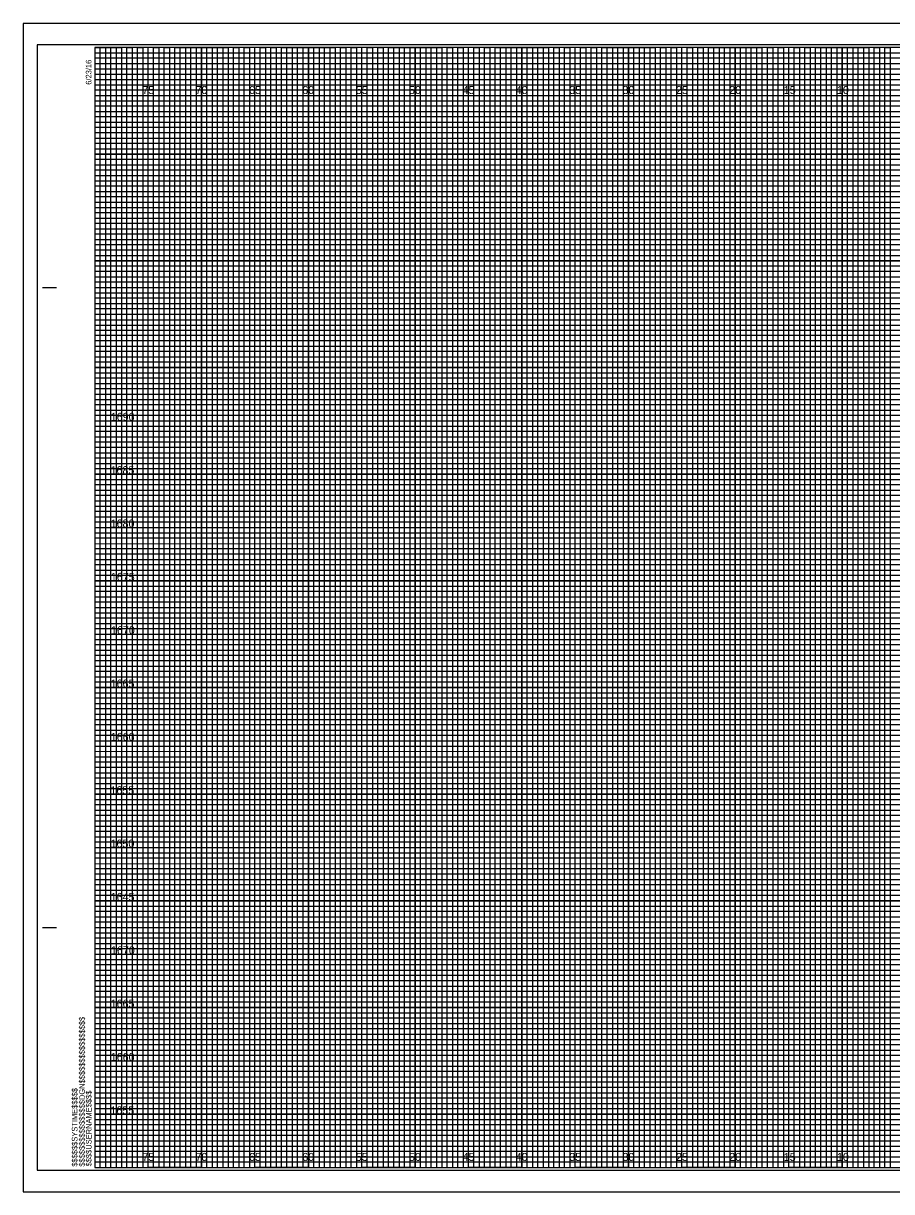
# Model space of a CAD drawing. Extents: x 224 to 392, y 1 to 440.
# Drawn here: x 223.6 to 304.9, y 1 to 110.5 of the extents above; entities that cross this region are included whole.
import ezdxf

# ---------------------------------------------------------------- set-up
doc = ezdxf.new("R2010")
doc.units = 0
for name, color, linetype in [('Prop Grid Mask', 7, 'Continuous'), ('Prop XS Elevation Labels', 7, 'Continuous'), ('Sheet Cross Section CELL', 7, 'Continuous'), ('Sheet Cross Section Grid Major CELL', 7, 'Continuous'), ('Sheet Cross Section Grid Middle CELL', 7, 'Continuous'), ('Sheet Cross Section Grid Minor 1 CELL', 7, 'Continuous'), ('Sheet Cross Section Grid Minor 2 CELL', 7, 'Continuous'), ('Sheet Cutting Line CELL', 7, 'Continuous'), ('Sheet DOT Grid CELL', 7, 'Continuous'), ('Sheet Plot Border Inside CELL', 7, 'Continuous'), ('Sheet Plot Border Outside CELL', 7, 'Continuous')]:
    doc.layers.add(name, color=color, linetype=linetype)

msp = doc.modelspace()

# ---------------------------------------------------------------- linework, layer by layer
at = {"layer": 'Sheet Cross Section CELL'}
for p, q in [((225.36, 85.71), (226.61, 85.71)), ((225.41, 85.71), (226.66, 85.71)), ((225.36, 25.71), (226.61, 25.71)), ((225.41, 25.71), (226.66, 25.71)), ((230.26, 3.21), (230.26, 3.21)), ((230.26, 3.21), (230.26, 3.21)), ((230.26, 3.21), (230.26, 3.21)), ((230.26, 3.21), (230.26, 3.21)), ((230.26, 3.21), (230.26, 3.21)), ((230.26, 3.21), (230.26, 3.21)), ((230.26, 3.21), (230.26, 3.21))]:
    msp.add_line(p, q, dxfattribs=at)
msp.add_lwpolyline([(390.26, 108.21), (230.26, 108.21), (230.26, 3.21), (390.26, 3.21)], close=True, dxfattribs=at)
at = {"layer": 'Sheet Cross Section Grid Major CELL'}
for p, q in [((235.26, 108.21), (230.26, 108.21)), ((235.26, 3.21), (235.26, 108.21)), ((245.26, 108.21), (240.26, 108.21)), ((240.26, 108.21), (240.26, 3.21)), ((245.26, 3.21), (245.26, 108.21)), ((255.26, 108.21), (250.26, 108.21)), ((250.26, 108.21), (250.26, 3.21)), ((255.26, 3.21), (255.26, 108.21)), ((265.26, 108.21), (260.26, 108.21)), ((260.26, 108.21), (260.26, 3.21)), ((265.26, 3.21), (265.26, 108.21)), ((275.26, 108.21), (270.26, 108.21)), ((270.26, 108.21), (270.26, 3.21)), ((275.26, 3.21), (275.26, 108.21)), ((285.26, 108.21), (280.26, 108.21)), ((280.26, 108.21), (280.26, 3.21)), ((285.26, 3.21), (285.26, 108.21)), ((295.26, 108.21), (290.26, 108.21)), ((290.26, 108.21), (290.26, 3.21)), ((295.26, 3.21), (295.26, 108.21)), ((305.26, 108.21), (300.26, 108.21)), ((300.26, 108.21), (300.26, 3.21)), ((240.26, 3.21), (235.26, 3.21)), ((250.26, 3.21), (245.26, 3.21)), ((260.26, 3.21), (255.26, 3.21)), ((270.26, 3.21), (265.26, 3.21)), ((280.26, 3.21), (275.26, 3.21)), ((290.26, 3.21), (285.26, 3.21)), ((300.26, 3.21), (295.26, 3.21))]:
    msp.add_line(p, q, dxfattribs=at)
for points in [[(230.26, 103.21), (390.26, 103.21), (390.26, 98.21), (230.26, 98.21)], [(230.26, 93.21), (390.26, 93.21), (390.26, 88.21), (230.26, 88.21)], [(230.26, 83.21), (390.26, 83.21), (390.26, 78.21), (230.26, 78.21)], [(230.26, 73.21), (390.26, 73.21), (390.26, 68.21), (230.26, 68.21)], [(230.26, 63.21), (390.26, 63.21), (390.26, 58.21), (230.26, 58.21)], [(230.26, 53.21), (390.26, 53.21), (390.26, 48.21), (230.26, 48.21)], [(230.26, 43.21), (390.26, 43.21), (390.26, 38.21), (230.26, 38.21)], [(230.26, 33.21), (390.26, 33.21), (390.26, 28.21), (230.26, 28.21)], [(230.26, 23.21), (390.26, 23.21), (390.26, 18.21), (230.26, 18.21)], [(230.26, 13.21), (390.26, 13.21), (390.26, 8.21), (230.26, 8.21)]]:
    msp.add_lwpolyline(points, dxfattribs=at)
at = {"layer": 'Sheet Cross Section Grid Middle CELL'}
for points in [[(230.26, 108.21), (232.76, 108.21), (232.76, 3.21), (237.76, 3.21), (237.76, 108.21), (242.76, 108.21), (242.76, 3.21), (247.76, 3.21), (247.76, 108.21), (252.76, 108.21), (252.76, 3.21), (257.76, 3.21), (257.76, 108.21), (262.76, 108.21), (262.76, 3.21), (267.76, 3.21), (267.76, 108.21), (272.76, 108.21), (272.76, 3.21), (277.76, 3.21), (277.76, 108.21), (282.76, 108.21), (282.76, 3.21), (287.76, 3.21), (287.76, 108.21), (292.76, 108.21), (292.76, 3.21), (297.76, 3.21), (297.76, 108.21), (302.76, 108.21), (302.76, 3.21), (307.76, 3.21)], [(230.26, 105.71), (367.76, 105.71)], [(230.26, 95.71), (390.26, 95.71), (390.26, 100.71), (230.26, 100.71)], [(230.26, 85.71), (390.26, 85.71), (390.26, 90.71), (230.26, 90.71)], [(230.26, 75.71), (390.26, 75.71), (390.26, 80.71), (230.26, 80.71)], [(230.26, 65.71), (390.26, 65.71), (390.26, 70.71), (230.26, 70.71)], [(230.26, 55.71), (390.26, 55.71), (390.26, 60.71), (230.26, 60.71)], [(230.26, 45.71), (390.26, 45.71), (390.26, 50.71), (230.26, 50.71)], [(230.26, 35.71), (390.26, 35.71), (390.26, 40.71), (230.26, 40.71)], [(230.26, 25.71), (390.26, 25.71), (390.26, 30.71), (230.26, 30.71)], [(230.26, 15.71), (390.26, 15.71), (390.26, 20.71), (230.26, 20.71)], [(230.26, 5.71), (390.26, 5.71), (390.26, 10.71), (230.26, 10.71)]]:
    msp.add_lwpolyline(points, dxfattribs=at)
at = {"layer": 'Sheet Cross Section Grid Minor 1 CELL'}
for p, q in [((230.26, 107.71), (360.26, 107.71)), ((360.26, 107.2), (230.26, 107.2)), ((230.26, 107.2), (230.26, 106.71)), ((230.26, 106.71), (360.26, 106.71)), ((360.26, 106.16), (230.26, 106.16)), ((230.26, 106.16), (230.26, 105.21)), ((230.26, 105.21), (390.26, 105.21))]:
    msp.add_line(p, q, dxfattribs=at)
for points in [[(230.26, 104.71), (365.26, 104.71), (390.26, 104.71), (390.26, 104.21), (230.26, 104.21)], [(230.26, 103.71), (390.26, 103.71), (390.26, 102.71), (230.26, 102.71)], [(230.26, 102.21), (390.26, 102.21), (390.26, 101.71), (230.26, 101.7)], [(230.26, 101.21), (390.26, 101.21), (390.26, 100.21), (230.26, 100.21)], [(230.26, 99.71), (390.26, 99.71), (390.26, 99.21), (230.26, 99.21)], [(230.26, 98.71), (390.26, 98.71), (390.26, 97.71), (230.26, 97.71)], [(230.26, 97.21), (390.26, 97.21), (390.26, 96.71), (230.26, 96.71)], [(230.26, 96.21), (390.26, 96.21), (390.26, 95.21), (230.26, 95.21)], [(230.26, 94.71), (390.26, 94.71), (390.26, 94.21), (230.26, 94.21)], [(230.26, 93.71), (390.26, 93.71), (390.26, 92.71), (230.26, 92.71)], [(230.26, 92.21), (390.26, 92.21), (390.26, 91.71), (230.26, 91.71)], [(230.26, 91.21), (390.26, 91.21), (390.26, 90.19), (390.26, 89.71), (390.26, 89.21), (230.26, 89.21)], [(230.26, 90.21), (390.26, 90.21), (390.26, 89.71), (230.26, 89.71)], [(230.26, 88.71), (390.26, 88.71), (390.26, 87.71), (230.26, 87.73)], [(230.26, 87.73), (390.26, 87.71), (390.26, 87.21), (230.26, 87.21)], [(230.26, 86.71), (390.26, 86.71), (390.26, 86.21), (230.26, 86.21)], [(230.26, 85.21), (390.26, 85.21), (390.26, 84.71), (230.26, 84.71)], [(230.26, 84.21), (390.26, 84.21), (390.26, 83.71), (230.26, 83.71)], [(230.23, 82.66), (390.26, 82.66), (390.26, 82.15), (230.23, 82.15)], [(230.26, 81.71), (390.26, 81.71), (390.26, 81.21), (230.26, 81.21)], [(230.26, 80.21), (390.26, 80.21), (390.26, 79.71), (230.26, 79.71)], [(230.26, 79.21), (390.26, 79.21), (390.26, 78.71), (230.26, 78.71)], [(230.26, 77.71), (390.26, 77.71), (390.26, 77.21), (230.26, 77.21)], [(230.26, 76.71), (390.26, 76.71), (390.26, 76.21), (230.26, 76.21)], [(230.26, 75.21), (390.26, 75.21), (390.26, 74.71), (230.26, 74.71)], [(230.26, 74.21), (390.26, 74.21), (390.26, 73.71), (230.26, 73.71)], [(230.26, 72.71), (390.26, 72.71), (390.26, 72.2), (230.26, 72.21)], [(230.26, 71.71), (390.26, 71.71), (390.26, 71.21), (230.26, 71.21)], [(230.26, 70.21), (390.26, 70.21), (390.26, 69.71), (230.26, 69.71)], [(230.26, 69.21), (390.26, 69.21), (390.26, 68.71), (230.26, 68.71)], [(230.26, 67.71), (390.26, 67.71), (390.26, 67.21), (230.26, 67.21)], [(230.26, 66.71), (390.26, 66.71), (390.26, 66.21), (230.26, 66.21)], [(230.26, 65.21), (390.26, 65.21), (390.26, 64.71), (230.26, 64.71)], [(230.26, 64.21), (390.26, 64.21), (390.26, 63.71), (230.26, 63.71)], [(230.26, 62.71), (390.26, 62.71), (390.26, 62.21), (230.26, 62.21)], [(230.26, 61.71), (390.3, 61.67), (390.26, 61.21), (230.26, 61.21)], [(230.26, 60.21), (390.26, 60.21), (390.26, 59.71), (230.26, 59.71)], [(230.26, 59.21), (390.26, 59.21), (390.26, 58.71), (230.26, 58.71)], [(230.26, 57.71), (390.26, 57.71), (390.26, 57.21), (230.26, 57.21)], [(230.26, 56.71), (390.26, 56.71), (390.26, 56.21), (230.26, 56.21)], [(230.26, 55.21), (390.26, 55.21), (390.26, 54.71), (230.26, 54.71)], [(230.26, 54.21), (390.26, 54.21), (390.26, 53.71), (230.26, 53.71)], [(230.26, 52.71), (390.26, 52.71), (390.26, 52.21), (230.26, 52.21)], [(230.26, 51.71), (390.26, 51.71), (390.26, 51.21), (230.26, 51.21)], [(230.26, 50.21), (390.26, 50.21), (390.26, 49.71), (230.26, 49.71)], [(230.26, 49.21), (390.26, 49.21), (390.26, 48.71), (230.26, 48.71)], [(230.26, 47.71), (390.26, 47.71), (390.26, 47.21), (230.26, 47.21)], [(230.26, 46.71), (390.26, 46.71), (390.26, 46.21), (230.26, 46.21)], [(230.26, 45.21), (390.26, 45.21), (390.26, 44.71), (230.26, 44.71)], [(230.26, 44.21), (390.26, 44.21), (390.26, 43.71), (230.26, 43.71)], [(230.26, 42.71), (390.26, 42.71), (390.26, 42.2), (230.26, 42.21)], [(230.26, 41.71), (390.26, 41.71), (390.26, 41.21), (230.26, 41.21)], [(230.26, 40.21), (390.26, 40.21), (390.26, 39.71), (230.26, 39.71)], [(230.26, 39.21), (390.26, 39.21), (390.26, 38.71), (230.26, 38.71)], [(230.26, 37.71), (390.26, 37.71), (390.26, 37.21), (230.26, 37.21)], [(230.26, 36.71), (390.26, 36.71), (390.26, 36.21), (230.26, 36.21)], [(230.26, 35.21), (390.26, 35.21), (390.26, 34.71), (230.26, 34.71)], [(230.26, 34.21), (390.26, 34.21), (390.26, 33.71), (230.26, 33.71)], [(230.26, 32.71), (390.26, 32.71), (390.26, 32.21), (230.26, 32.21)], [(230.26, 31.71), (390.3, 31.67), (390.26, 31.21), (230.26, 31.21)], [(230.26, 30.21), (390.26, 30.21), (390.26, 29.71), (230.26, 29.71)], [(230.26, 29.21), (390.26, 29.21), (390.26, 28.71), (230.26, 28.71)], [(230.26, 27.71), (390.26, 27.71), (390.26, 27.21), (230.26, 27.21)], [(230.26, 26.71), (390.26, 26.71), (390.26, 26.21), (230.26, 26.21)], [(230.26, 25.21), (390.26, 25.21), (390.26, 24.71), (230.26, 24.71)], [(230.26, 24.21), (390.26, 24.21), (390.26, 23.71), (230.26, 23.71)], [(230.26, 22.71), (390.26, 22.71), (390.26, 22.21), (230.26, 22.21)], [(230.26, 21.71), (390.26, 21.71), (390.26, 21.21), (230.26, 21.21)], [(230.26, 20.21), (390.26, 20.21), (390.26, 19.71), (230.26, 19.71)], [(230.26, 19.21), (390.26, 19.21), (390.26, 18.71), (230.26, 18.71)], [(230.26, 17.71), (390.26, 17.71), (390.26, 17.21), (230.26, 17.21)], [(230.26, 16.71), (390.26, 16.71), (390.26, 16.21), (230.26, 16.21)], [(230.26, 15.21), (390.26, 15.21), (390.26, 14.71), (230.26, 14.71)], [(230.26, 14.21), (390.26, 14.21), (390.26, 13.71), (230.26, 13.71)], [(230.26, 12.71), (390.26, 12.71), (390.26, 12.21), (230.26, 12.21)], [(230.26, 11.71), (390.26, 11.71), (390.26, 11.21), (230.26, 11.21)], [(230.26, 10.21), (390.26, 10.21), (390.26, 9.71), (230.26, 9.71)], [(230.26, 9.21), (390.26, 9.21), (390.26, 8.71), (230.26, 8.71)], [(230.26, 7.71), (390.26, 7.71), (390.26, 7.21), (230.26, 7.21)], [(230.26, 6.71), (390.26, 6.71), (390.26, 6.21), (230.26, 6.21)], [(230.26, 5.21), (390.26, 5.21), (390.26, 4.71), (230.26, 4.71)], [(230.26, 4.21), (390.26, 4.21), (390.26, 3.71), (230.26, 3.71)]]:
    msp.add_lwpolyline(points, dxfattribs=at)
at = {"layer": 'Sheet Cross Section Grid Minor 2 CELL'}
for points in [[(230.26, 3.21), (230.76, 3.21), (230.76, 108.21), (231.26, 108.21), (231.26, 3.21)], [(231.26, 3.21), (231.76, 3.21), (231.76, 108.21), (232.26, 108.21), (232.26, 3.21)], [(232.76, 3.21), (233.26, 3.21), (233.26, 108.21), (233.76, 108.21), (233.76, 3.21)], [(233.76, 3.21), (234.26, 3.21), (234.26, 108.21), (234.76, 108.21), (234.76, 3.21)], [(235.26, 3.21), (235.76, 3.21), (235.76, 108.21), (236.26, 108.21), (236.26, 3.21)], [(236.26, 3.21), (236.76, 3.21), (236.76, 108.21), (237.26, 108.21), (237.26, 3.21)], [(237.76, 3.21), (238.26, 3.21), (238.26, 108.21), (238.76, 108.21), (238.76, 3.21)], [(238.76, 3.21), (239.26, 3.21), (239.26, 108.21), (239.76, 108.21), (239.76, 3.21)], [(240.26, 3.21), (240.76, 3.21), (240.76, 108.21), (241.26, 108.21), (241.26, 3.21)], [(241.26, 3.21), (241.76, 3.21), (241.76, 108.21), (242.26, 108.21), (242.26, 3.21)], [(242.76, 3.21), (243.26, 3.21), (243.26, 108.21), (243.76, 108.21), (243.76, 3.21)], [(243.76, 3.21), (244.26, 3.21), (244.26, 108.21), (244.76, 108.21), (244.76, 3.21)], [(245.26, 3.21), (245.76, 3.21), (245.76, 108.21), (246.26, 108.21), (246.26, 3.21)], [(246.26, 3.21), (246.76, 3.21), (246.76, 108.21), (247.26, 108.21), (247.26, 3.21)], [(247.76, 3.21), (248.26, 3.21), (248.26, 108.21), (248.76, 108.21), (248.76, 3.21)], [(248.76, 3.21), (249.26, 3.21), (249.26, 108.21), (249.76, 108.21), (249.76, 3.21)], [(250.26, 3.21), (250.76, 3.21), (250.76, 108.21), (251.26, 108.21), (251.26, 3.21)], [(251.26, 3.21), (251.76, 3.21), (251.76, 108.21), (252.26, 108.21), (252.26, 3.21)], [(252.76, 3.21), (253.26, 3.21), (253.26, 108.21), (253.76, 108.21), (253.76, 3.21)], [(253.76, 3.21), (254.26, 3.21), (254.26, 108.21), (254.76, 108.21), (254.76, 3.21)], [(255.26, 3.21), (255.76, 3.21), (255.76, 108.21), (256.26, 108.21), (256.26, 3.21)], [(256.26, 3.21), (256.76, 3.21), (256.76, 108.21), (257.26, 108.21), (257.26, 3.21)], [(257.76, 3.21), (258.26, 3.21), (258.26, 108.21), (258.76, 108.21), (258.76, 3.21)], [(258.76, 3.21), (259.26, 3.21), (259.26, 108.21), (259.76, 108.21), (259.76, 3.21)], [(260.26, 3.21), (260.76, 3.21), (260.76, 108.21), (261.26, 108.21), (261.26, 3.21)], [(261.26, 3.21), (261.76, 3.21), (261.76, 108.21), (262.26, 108.21), (262.26, 3.21)], [(262.76, 3.21), (263.26, 3.21), (263.26, 108.21), (263.76, 108.21), (263.76, 3.21)], [(263.76, 3.21), (264.26, 3.21), (264.26, 108.21), (264.76, 108.21), (264.76, 3.21)], [(265.26, 3.21), (265.76, 3.21), (265.76, 108.21), (266.26, 108.21), (266.26, 3.21)], [(266.26, 3.21), (266.76, 3.21), (266.76, 108.21), (267.26, 108.21), (267.26, 3.21)], [(267.76, 3.21), (268.26, 3.21), (268.26, 108.21), (268.76, 108.21), (268.76, 3.21)], [(268.76, 3.21), (269.26, 3.21), (269.26, 108.21), (269.76, 108.21), (269.76, 3.21)], [(270.26, 3.21), (270.76, 3.21), (270.76, 108.21), (271.26, 108.21), (271.26, 3.21)], [(271.26, 3.21), (271.76, 3.21), (271.76, 108.21), (272.26, 108.21), (272.26, 3.21)], [(272.76, 3.21), (273.26, 3.21), (273.26, 108.21), (273.76, 108.21), (273.76, 3.21)], [(273.76, 3.21), (274.26, 3.21), (274.26, 108.21), (274.76, 108.21), (274.76, 3.21)], [(275.26, 3.21), (275.76, 3.21), (275.76, 108.21), (276.26, 108.21), (276.26, 3.21)], [(276.26, 3.21), (276.76, 3.21), (276.76, 108.21), (277.26, 108.21), (277.26, 3.21)], [(277.76, 3.21), (278.26, 3.21), (278.26, 108.21), (278.76, 108.21), (278.76, 3.21)], [(278.76, 3.21), (279.26, 3.21), (279.26, 108.21), (279.76, 108.21), (279.76, 3.21)], [(280.26, 3.21), (280.76, 3.21), (280.76, 108.21), (281.26, 108.21), (281.26, 3.21)], [(281.26, 3.21), (281.76, 3.21), (281.76, 108.21), (282.26, 108.21), (282.26, 3.21)], [(282.76, 3.21), (283.26, 3.21), (283.26, 108.21), (283.76, 108.21), (283.76, 3.21)], [(283.76, 3.21), (284.26, 3.21), (284.26, 108.21), (284.76, 108.21), (284.76, 3.21)], [(285.26, 3.21), (285.76, 3.21), (285.76, 108.21), (286.26, 108.21), (286.26, 3.21)], [(286.26, 3.21), (286.76, 3.21), (286.76, 108.21), (287.26, 108.21), (287.26, 3.21)], [(287.76, 3.21), (288.26, 3.21), (288.26, 108.21), (288.76, 108.21), (288.76, 3.21)], [(288.76, 3.21), (289.26, 3.21), (289.26, 108.21), (289.76, 108.21), (289.76, 3.21)], [(290.26, 3.21), (290.76, 3.21), (290.76, 108.21), (291.26, 108.21), (291.26, 3.21)], [(291.26, 3.21), (291.76, 3.21), (291.76, 108.21), (292.26, 108.21), (292.26, 3.21)], [(292.76, 3.21), (293.26, 3.21), (293.26, 108.21), (293.76, 108.21), (293.76, 3.21)], [(293.76, 3.21), (294.26, 3.21), (294.26, 108.21), (294.76, 108.21), (294.76, 3.21)], [(295.26, 3.21), (295.76, 3.21), (295.76, 108.21), (296.26, 108.21), (296.26, 3.21)], [(296.26, 3.21), (296.76, 3.21), (296.76, 108.21), (297.26, 108.21), (297.26, 3.21)], [(297.76, 3.21), (298.26, 3.21), (298.26, 108.21), (298.76, 108.21), (298.76, 3.21)], [(298.76, 3.21), (299.26, 3.21), (299.26, 108.21), (299.76, 108.21), (299.76, 3.21)], [(300.26, 3.21), (300.76, 3.21), (300.76, 108.21), (301.26, 108.21), (301.26, 3.21)], [(301.26, 3.21), (301.76, 3.21), (301.76, 108.21), (302.26, 108.21), (302.26, 3.21)], [(302.76, 3.21), (303.26, 3.21), (303.26, 108.21), (303.76, 108.21), (303.76, 3.21)], [(303.76, 3.21), (304.26, 3.21), (304.26, 108.21), (304.76, 108.21), (304.76, 3.21)]]:
    msp.add_lwpolyline(points, dxfattribs=at)
at = {"layer": 'Sheet Cutting Line CELL'}
for p, q in [((391.91, 110.46), (223.56, 110.46)), ((223.56, 110.46), (223.56, 0.96)), ((223.56, 0.96), (391.91, 0.96))]:
    msp.add_line(p, q, dxfattribs=at)
at = {"layer": 'Sheet DOT Grid CELL'}
for p, q in [((235.26, 3.21), (235.26, 108.21)), ((240.26, 3.21), (240.26, 108.21)), ((245.26, 3.21), (245.26, 108.21)), ((250.26, 3.21), (250.26, 108.21)), ((255.26, 3.21), (255.26, 108.21)), ((260.26, 3.21), (260.26, 108.21)), ((265.26, 3.21), (265.26, 108.21)), ((270.26, 3.21), (270.26, 108.21)), ((275.26, 3.21), (275.26, 108.21)), ((280.26, 3.21), (280.26, 108.21)), ((285.26, 3.21), (285.26, 108.21)), ((290.26, 3.21), (290.26, 108.21)), ((295.26, 3.21), (295.26, 108.21)), ((300.26, 3.21), (300.26, 108.21)), ((230.26, 103.21), (390.26, 103.21)), ((230.26, 98.21), (390.26, 98.21)), ((230.26, 93.21), (390.26, 93.21)), ((230.26, 88.21), (390.26, 88.21)), ((230.26, 83.21), (390.26, 83.21)), ((230.26, 78.21), (390.26, 78.21)), ((230.26, 73.21), (390.26, 73.21)), ((230.26, 68.21), (390.26, 68.21)), ((230.26, 63.21), (390.26, 63.21)), ((230.26, 58.21), (390.26, 58.21)), ((230.26, 53.21), (390.26, 53.21)), ((230.26, 48.21), (390.26, 48.21)), ((230.26, 43.21), (390.26, 43.21)), ((230.26, 38.21), (390.26, 38.21)), ((230.26, 33.21), (390.26, 33.21)), ((230.26, 28.21), (390.26, 28.21)), ((230.26, 23.21), (390.26, 23.21)), ((230.26, 18.21), (390.26, 18.21)), ((230.26, 13.21), (390.26, 13.21)), ((230.26, 8.21), (390.26, 8.21))]:
    msp.add_line(p, q, dxfattribs=at)
at = {"layer": 'Sheet Plot Border Inside CELL'}
msp.add_lwpolyline([(224.86, 2.96), (391.46, 2.96), (391.46, 108.46), (224.86, 108.46)], close=True, dxfattribs=at)
at = {"layer": 'Sheet Plot Border Outside CELL'}
msp.add_lwpolyline([(223.56, 0.96), (391.91, 0.96), (391.91, 110.46), (223.56, 110.46)], close=True, dxfattribs=at)

# ---------------------------------------------------------------- texts
at = {"layer": 'Prop Grid Mask'}
for s, p in [('75', (234.71, 103.84)), ('70', (239.69, 103.84)), ('65', (244.71, 103.84)), ('60', (249.69, 103.84)), ('55', (254.71, 103.84)), ('50', (259.69, 103.84)), ('45', (264.71, 103.84)), ('40', (269.69, 103.84)), ('35', (274.71, 103.84)), ('30', (279.69, 103.84)), ('25', (284.71, 103.84)), ('20', (289.69, 103.84)), ('15', (294.8, 103.84)), ('10', (299.78, 103.84)), ('75', (234.71, 3.84)), ('70', (239.69, 3.84)), ('65', (244.71, 3.84)), ('60', (249.69, 3.84)), ('55', (254.71, 3.84)), ('50', (259.69, 3.84)), ('45', (264.71, 3.84)), ('40', (269.69, 3.84)), ('35', (274.71, 3.84)), ('30', (279.69, 3.84)), ('25', (284.71, 3.84)), ('20', (289.69, 3.84)), ('15', (294.8, 3.84)), ('10', (299.78, 3.84))]:
    msp.add_text(s, height=0.75, dxfattribs=at).set_placement(p)
at = {"layer": 'Prop XS Elevation Labels'}
for s, p in [('1690', (231.75, 73.21)), ('1685', (231.73, 68.21)), ('1680', (231.74, 63.21)), ('1675', (231.76, 58.21)), ('1670', (231.77, 53.21)), ('1665', (231.74, 48.21)), ('1660', (231.75, 43.21)), ('1655', (231.72, 38.21)), ('1650', (231.73, 33.21)), ('1645', (231.74, 28.21)), ('1670', (231.77, 23.21)), ('1665', (231.74, 18.21)), ('1660', (231.75, 13.21)), ('1655', (231.72, 8.21))]:
    msp.add_text(s, height=0.75, dxfattribs=at).set_placement(p)
at = {"layer": 'Sheet Cross Section CELL'}
for s, p in [('6/23/16', (229.94, 104.71)), ('$$$$$$$$$$$$$$$$DGN$$$$$$$$$$$$$$$$', (229.32, 3.3)), ('$$$$$$SYSTIME$$$$$', (228.63, 3.3)), ('$$$$USERNAME$$$$', (229.95, 3.33))]:
    msp.add_text(s, height=0.525, rotation=90, dxfattribs=at).set_placement(p)

doc.saveas('drawing.dxf')
